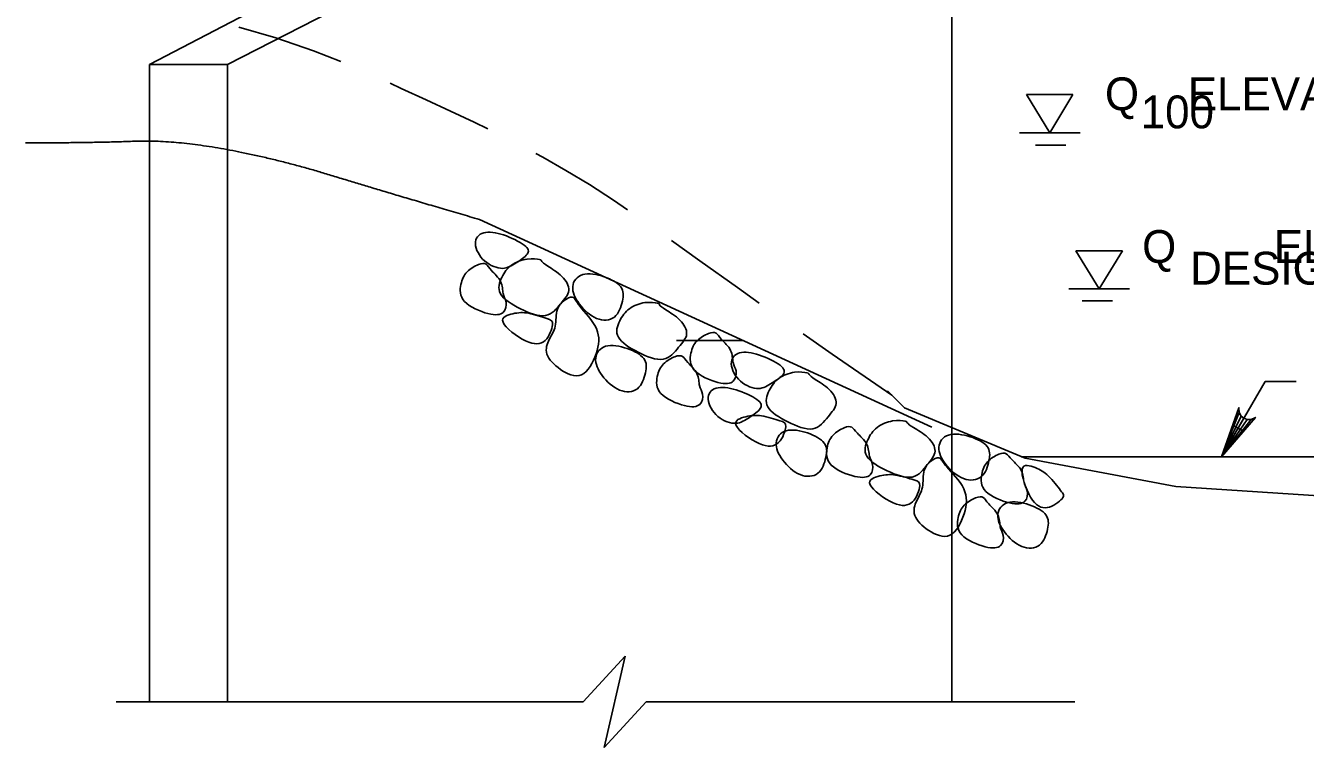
# Model space of a CAD drawing. Extents: x 638268 to 640277, y 295465 to 298435.
# Drawn here: x 638485.1 to 638602.1, y 296759.6 to 296825.5 of the extents above; entities that cross this region are included whole.
import ezdxf

# ---------------------------------------------------------------- set-up
doc = ezdxf.new("R2010")
doc.units = 0
for name, color, linetype in [('3', 7, 'Continuous'), ('4', 7, 'Continuous'), ('8', 7, 'Continuous')]:
    doc.layers.add(name, color=color, linetype=linetype)

msp = doc.modelspace()

# ---------------------------------------------------------------- linework, layer by layer
at = {"layer": '3'}
for p, q in [((638561.57, 296855.85), (638496.45, 296821.97)), ((638569.79, 296855.85), (638503.58, 296821.97)), ((638569.79, 296851.52), (638569.79, 296788.79)), ((638503.58, 296821.97), (638496.45, 296821.97)), ((638496.45, 296821.97), (638496.45, 296814.85)), ((638503.58, 296814.09), (638503.58, 296821.97)), ((638496.45, 296814.85), (638496.45, 296763.74)), ((638503.58, 296763.74), (638503.58, 296814.09)), ((638526.61, 296807.8), (638567.98, 296788.82)), ((638544.63, 296796.73), (638550.73, 296796.73)), ((638569.79, 296788.79), (638569.79, 296763.74)), ((638576.14, 296786.13), (638736.87, 296786.13)), ((638536.09, 296763.74), (638539.93, 296767.92)), ((638539.93, 296767.92), (638538.01, 296759.57)), ((638493.41, 296763.74), (638536.09, 296763.74)), ((638538.01, 296759.57), (638541.85, 296763.74)), ((638541.85, 296763.74), (638581.05, 296763.74))]:
    msp.add_line(p, q, dxfattribs=at)
for points, degree in [([(638526.61, 296807.8), (638518.08, 296810.29), (638508.15, 296813.34), (638498.62, 296815.09), (638491.28, 296814.8), (638485.12, 296814.8)], 2), ([(638530.89, 296804.53), (638530.65, 296804.27), (638529.78, 296803.72), (638528.68, 296803.08), (638526.7, 296804.02), (638525.94, 296805.94), (638527.03, 296806.85), (638529.05, 296806.41), (638531.23, 296805.27), (638531.14, 296804.79), (638530.89, 296804.53)], 3), ([(638532.31, 296803.97), (638532.36, 296803.89), (638532.69, 296803.6), (638534.28, 296802.69), (638535.07, 296801.25), (638534.07, 296800.2), (638532.87, 296798.58), (638530.29, 296799.58), (638528.07, 296800.99), (638528.62, 296802.59), (638529.41, 296803.71), (638531.01, 296804.32), (638532.36, 296804.11), (638532.25, 296804.06), (638532.31, 296803.97)], 3), ([(638528.77, 296801.03), (638528.84, 296800.73), (638529.14, 296800.37), (638528.99, 296799.14), (638527.65, 296798.97), (638524.75, 296800.22), (638524.85, 296801.98), (638525.36, 296803.08), (638526.62, 296803.79), (638527.27, 296803.82), (638527.57, 296803.2), (638528.75, 296802.17), (638528.71, 296801.33), (638528.77, 296801.03)], 3), ([(638539.53, 296801.64), (638539.81, 296801.26), (638539.77, 296800.43), (638539.15, 296798.6), (638537.31, 296798.47), (638535.56, 296800.09), (638534.86, 296801.72), (638535.83, 296803.06), (638538.1, 296802.65), (638539.26, 296802.01), (638539.53, 296801.64)], 3), ([(638535.21, 296800.67), (638535.35, 296800.58), (638535.46, 296800.12), (638537.72, 296797.81), (638537.47, 296795.6), (638536.08, 296793.01), (638533.88, 296794.02), (638532.47, 296795.53), (638532.94, 296796.9), (638533.69, 296797.92), (638533.54, 296799.76), (638534.63, 296800.66), (638535.07, 296800.76), (638535.21, 296800.67)], 3), ([(638532.76, 296798.75), (638533.18, 296798.6), (638533.49, 296798.5), (638532.78, 296796.44), (638531.06, 296796.27), (638527.94, 296798.74), (638529.78, 296799.26), (638530.97, 296799.37), (638532.34, 296798.89), (638532.76, 296798.75)], 3), ([(638543.08, 296799.99), (638543.14, 296799.91), (638543.47, 296799.62), (638545.06, 296798.7), (638545.85, 296797.27), (638544.85, 296796.22), (638543.64, 296794.59), (638541.07, 296795.6), (638538.85, 296797.01), (638539.39, 296798.61), (638540.18, 296799.73), (638541.78, 296800.34), (638543.13, 296800.13), (638543.03, 296800.08), (638543.08, 296799.99)], 3), ([(638549.8, 296794.74), (638549.86, 296794.44), (638550.17, 296794.07), (638550.01, 296792.85), (638548.67, 296792.68), (638545.78, 296793.93), (638545.87, 296795.69), (638546.38, 296796.79), (638547.64, 296797.49), (638548.3, 296797.52), (638548.6, 296796.91), (638549.77, 296795.88), (638549.73, 296795.04), (638549.8, 296794.74)], 3), ([(638541.64, 296795.09), (638541.92, 296794.71), (638541.88, 296793.88), (638541.25, 296792.05), (638539.41, 296791.92), (638537.66, 296793.54), (638536.96, 296795.17), (638537.93, 296796.51), (638540.2, 296796.1), (638541.36, 296795.46), (638541.64, 296795.09)], 3), ([(638546.73, 296792.62), (638546.8, 296792.32), (638547.1, 296791.95), (638546.95, 296790.73), (638545.6, 296790.56), (638542.71, 296791.81), (638542.8, 296793.57), (638543.32, 296794.67), (638544.58, 296795.37), (638545.23, 296795.4), (638545.53, 296794.79), (638546.7, 296793.76), (638546.66, 296792.92), (638546.73, 296792.62)], 3), ([(638554.28, 296793.55), (638554.04, 296793.29), (638553.17, 296792.74), (638552.07, 296792.1), (638550.09, 296793.03), (638549.33, 296794.96), (638550.42, 296795.87), (638552.44, 296795.43), (638554.62, 296794.29), (638554.52, 296793.81), (638554.28, 296793.55)], 3), ([(638556.75, 296793.64), (638556.8, 296793.55), (638557.13, 296793.27), (638558.72, 296792.35), (638559.52, 296790.92), (638558.51, 296789.87), (638557.31, 296788.24), (638554.73, 296789.24), (638552.51, 296790.65), (638553.06, 296792.25), (638553.85, 296793.37), (638555.45, 296793.98), (638556.8, 296793.77), (638556.69, 296793.72), (638556.75, 296793.64)], 3), ([(638552.2, 296790.43), (638551.97, 296790.17), (638551.11, 296789.59), (638550.02, 296788.92), (638548.02, 296789.8), (638547.21, 296791.72), (638548.27, 296792.65), (638550.31, 296792.26), (638552.51, 296791.18), (638552.43, 296790.69), (638552.2, 296790.43)], 3), ([(638554.06, 296789.42), (638554.48, 296789.29), (638554.79, 296789.19), (638554.14, 296787.12), (638552.42, 296786.9), (638549.24, 296789.28), (638551.07, 296789.85), (638552.25, 296789.99), (638553.64, 296789.55), (638554.06, 296789.42)], 3), ([(638562.27, 296786.19), (638562.34, 296785.89), (638562.65, 296785.53), (638562.53, 296784.3), (638561.19, 296784.1), (638558.27, 296785.27), (638558.32, 296787.03), (638558.8, 296788.14), (638560.04, 296788.88), (638560.7, 296788.93), (638561.01, 296788.33), (638562.21, 296787.33), (638562.19, 296786.49), (638562.27, 296786.19)], 3), ([(638565.72, 296789.22), (638565.78, 296789.14), (638566.12, 296788.86), (638567.73, 296787.98), (638568.56, 296786.57), (638567.58, 296785.5), (638566.42, 296783.84), (638563.82, 296784.77), (638561.56, 296786.13), (638562.07, 296787.74), (638562.83, 296788.88), (638564.42, 296789.53), (638565.77, 296789.36), (638565.66, 296789.3), (638565.72, 296789.22)], 3), ([(638558.13, 296787.37), (638558.41, 296787), (638558.37, 296786.16), (638557.75, 296784.33), (638555.9, 296784.2), (638554.16, 296785.82), (638553.46, 296787.46), (638554.43, 296788.79), (638556.7, 296788.39), (638557.85, 296787.74), (638558.13, 296787.37)], 3), ([(638573.01, 296787.07), (638573.3, 296786.7), (638573.28, 296785.87), (638572.7, 296784.02), (638570.86, 296783.84), (638569.07, 296785.42), (638568.33, 296787.03), (638569.27, 296788.39), (638571.55, 296788.05), (638572.72, 296787.43), (638573.01, 296787.07)], 3), ([(638576.4, 296783.77), (638576.48, 296783.47), (638576.79, 296783.11), (638576.67, 296781.88), (638575.33, 296781.68), (638572.41, 296782.85), (638572.45, 296784.61), (638572.94, 296785.73), (638574.18, 296786.47), (638574.83, 296786.51), (638575.15, 296785.91), (638576.35, 296784.91), (638576.33, 296784.07), (638576.4, 296783.77)], 3), ([(638568.71, 296785.99), (638568.85, 296785.9), (638568.98, 296785.45), (638571.3, 296783.2), (638571.11, 296780.98), (638569.77, 296778.36), (638567.55, 296779.31), (638566.1, 296780.78), (638566.53, 296782.17), (638567.26, 296783.2), (638567.07, 296785.04), (638568.13, 296785.97), (638568.57, 296786.07), (638568.71, 296785.99)], 3), ([(638579.74, 296783.05), (638580.01, 296782.7), (638580.21, 296782.45), (638578.48, 296781.12), (638576.95, 296781.92), (638575.71, 296785.7), (638577.54, 296785.13), (638578.58, 296784.55), (638579.47, 296783.4), (638579.74, 296783.05)], 3), ([(638566.31, 296784.01), (638566.74, 296783.87), (638567.04, 296783.78), (638566.39, 296781.7), (638564.67, 296781.48), (638561.49, 296783.87), (638563.32, 296784.44), (638564.51, 296784.58), (638565.89, 296784.14), (638566.31, 296784.01)], 3), ([(638574.22, 296779.72), (638574.29, 296779.42), (638574.59, 296779.05), (638574.44, 296777.83), (638573.1, 296777.66), (638570.2, 296778.91), (638570.3, 296780.67), (638570.81, 296781.77), (638572.07, 296782.48), (638572.72, 296782.51), (638573.02, 296781.89), (638574.19, 296780.86), (638574.16, 296780.02), (638574.22, 296779.72)], 3), ([(638578.4, 296780.81), (638578.67, 296780.44), (638578.64, 296779.6), (638578.01, 296777.77), (638576.17, 296777.64), (638574.42, 296779.26), (638573.72, 296780.89), (638574.69, 296782.23), (638576.96, 296781.82), (638578.12, 296781.18), (638578.4, 296780.81)], 3)]:
    msp.add_open_spline(points, degree=degree, dxfattribs=at)
at = {"layer": '4'}
for p, q in [((638576.62, 296819.22), (638578.74, 296815.73)), ((638576.62, 296819.22), (638580.86, 296819.22)), ((638580.86, 296819.22), (638578.74, 296815.73)), ((638578.74, 296815.73), (638575.97, 296815.73)), ((638578.74, 296815.73), (638581.51, 296815.73)), ((638577.43, 296814.59), (638580.2, 296814.59)), ((638581.14, 296804.94), (638585.38, 296804.94)), ((638581.14, 296804.94), (638583.26, 296801.45)), ((638585.38, 296804.94), (638583.26, 296801.45)), ((638583.26, 296801.45), (638580.49, 296801.45)), ((638583.26, 296801.45), (638586.03, 296801.45)), ((638581.71, 296800.37), (638584.48, 296800.37)), ((638594.44, 296786.13), (638598.45, 296792.99)), ((638598.45, 296792.99), (638601.26, 296792.99))]:
    msp.add_line(p, q, dxfattribs=at)
for points in [[(638605.67, 296782.41), (638590.26, 296783.41), (638576.51, 296785.98), (638565.47, 296790.6), (638563.9, 296792.16)], [(638594.44, 296786.13), (638596.04, 296790.6), (638596.07, 296790.16), (638596.25, 296789.84), (638596.49, 296789.64), (638596.79, 296789.53), (638597.15, 296789.53), (638597.55, 296789.72), (638594.44, 296786.13), (638597.15, 296789.53), (638596.79, 296789.53), (638594.44, 296786.13), (638596.49, 296789.64), (638596.25, 296789.84), (638594.44, 296786.13), (638596.07, 296790.16)]]:
    msp.add_lwpolyline(points, dxfattribs=at)
msp.add_lwpolyline([(638595.55, 296788.98), (638596.37, 296788.49), (638594.5, 296786.25)], close=True, dxfattribs=at)
at = {"layer": '8'}
for p, q in [((638508.01, 296824.39), (638504.63, 296825.38)), ((638511.45, 296823.2), (638508.01, 296824.39)), ((638513.94, 296822.22), (638511.45, 296823.2)), ((638519.45, 296819.77), (638518.45, 296820.24)), ((638521.75, 296818.72), (638519.45, 296819.77)), ((638523.96, 296817.69), (638521.75, 296818.72)), ((638526.12, 296816.68), (638523.96, 296817.69)), ((638527.37, 296816.08), (638526.12, 296816.68)), ((638532.42, 296813.48), (638531.75, 296813.84)), ((638534.52, 296812.29), (638532.42, 296813.48)), ((638536.66, 296810.99), (638534.52, 296812.29)), ((638538.85, 296809.57), (638536.66, 296810.99)), ((638540.13, 296808.69), (638538.85, 296809.57)), ((638546.76, 296804.02), (638544.16, 296805.87)), ((638550.19, 296801.58), (638546.76, 296804.02)), ((638552.19, 296800.17), (638550.19, 296801.58)), ((638558.86, 296795.49), (638556.21, 296797.34)), ((638564.31, 296791.75), (638558.86, 296795.49))]:
    msp.add_line(p, q, dxfattribs=at)

# ---------------------------------------------------------------- texts
at = {"layer": '4'}
for s, p in [('Q    ELEVATION - ', (638583.79, 296817.78)), ('100', (638587.06, 296816.13)), ('Q        ELEVATION - ', (638587.19, 296803.83)), ('DESIGN', (638591.58, 296801.85))]:
    msp.add_text(s, height=3, dxfattribs=at).set_placement(p)

doc.saveas('drawing.dxf')
